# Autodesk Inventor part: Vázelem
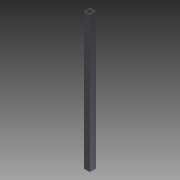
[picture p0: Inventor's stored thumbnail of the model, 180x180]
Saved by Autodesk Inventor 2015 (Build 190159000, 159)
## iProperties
Created: 2013-02
Part Number: Vázelem
Material: Generic
Document SubType Name: Modeling
Designer: Marci
Density: 1 g/cm^3
Appearance: Gray
Author: Marci
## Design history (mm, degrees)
sketch "Sketch1"
  geometry: L1 (0, 15)-(15, 15); L2 (15, 15)-(15, -15); L3 (15, -15)-(-15, -15); L4 (-15, -15)-(-15, 15); L5 (-15, 15)-(0, 15); L6 (-12, 12)-(-12, -12); L7 (-12, -12)-(12, -12); L8 (12, -12)-(12, 12); L9 (12, 12)-(0, 12); L10 (0, 12)-(-12, 12); 1 further point
  constraints: 20 end point, 2 collinear, 2 parallel, 4 other
  dimensions: "d0" = 15 distance of point (0, 0) L1.start; "d1" = 15 distance of L1.start L1.end; "d2" = 30 distance of L1.end L2.end; "d3" = 30 distance of L2.end L3.end; "d4" = 3 distance between parallel lines of L4 L6
extrude "Extrusion1" new body sketch "Sketch1" distance "d5" = 700; taper "d6" = 0 deg
body "Solid1"
